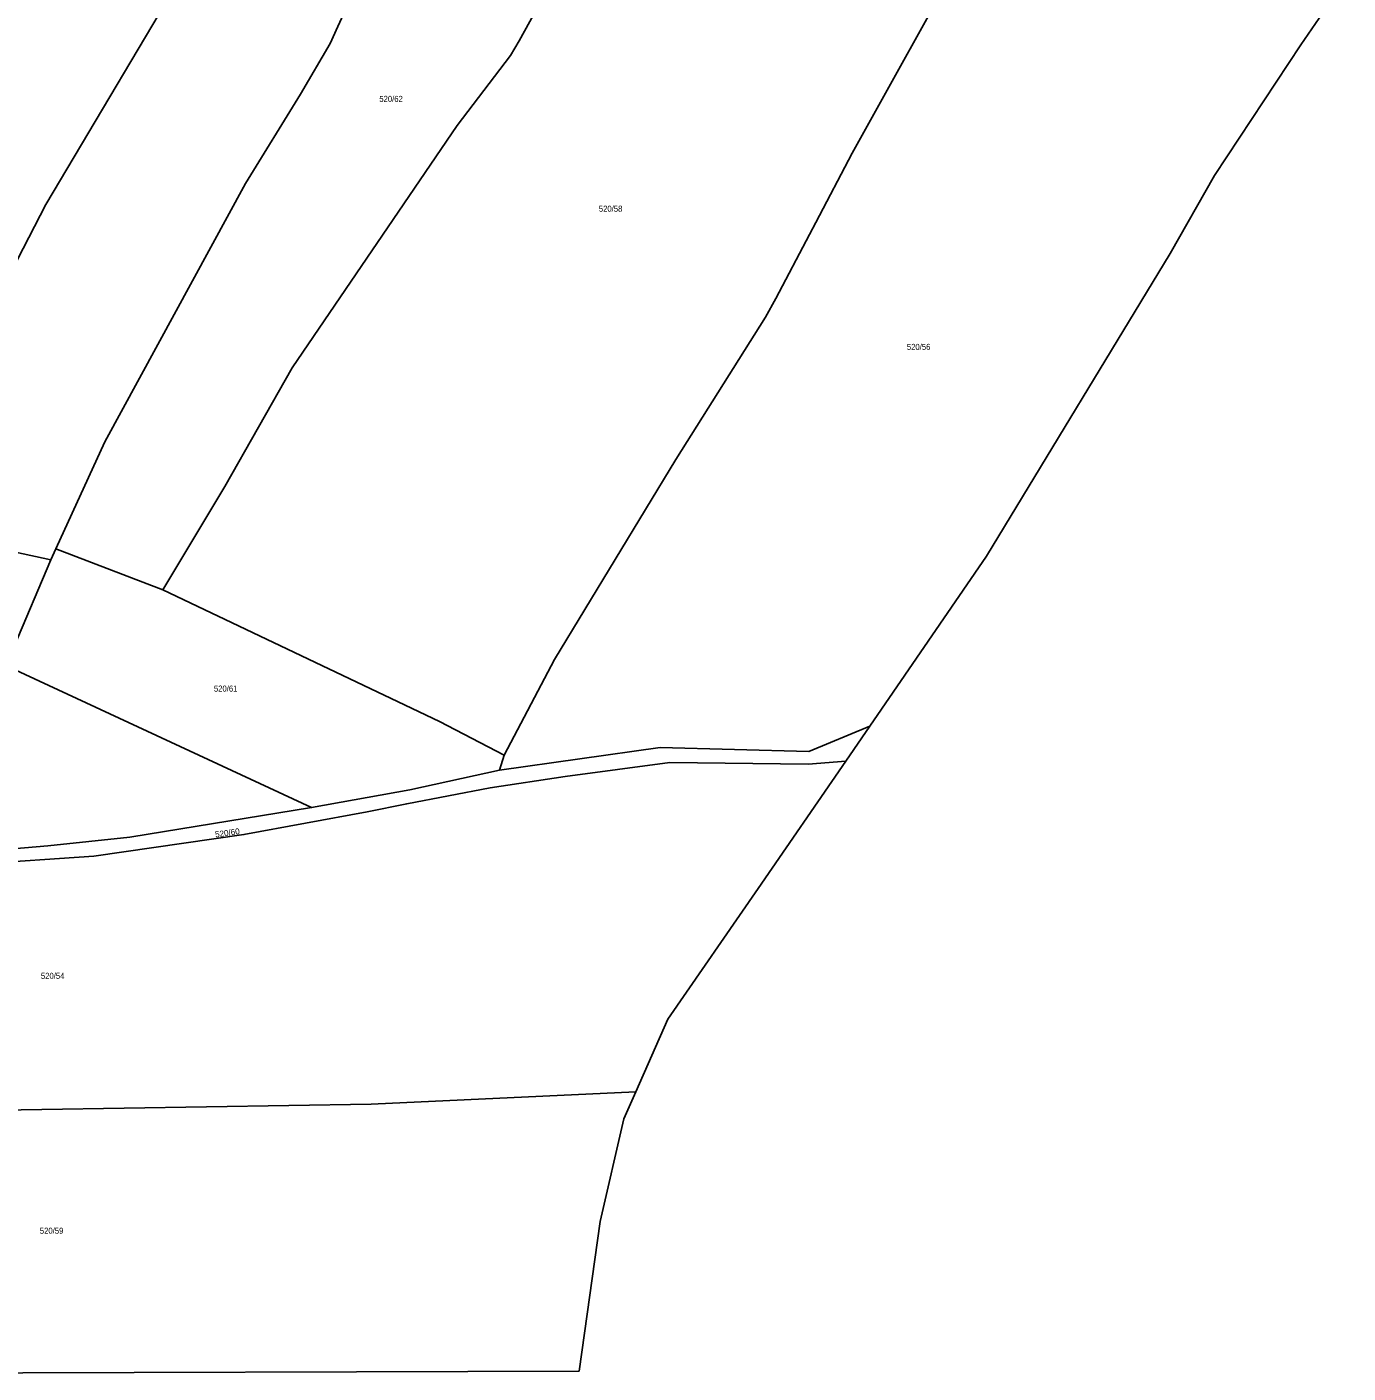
# Model space of a CAD drawing. Extents: x -687135 to -684370, y -1007309 to -1005782.
# Drawn here: x -685309.9 to -684938.9, y -1007302.2 to -1006924.3 of the extents above; entities that cross this region are included whole.
import ezdxf

# ---------------------------------------------------------------- set-up
doc = ezdxf.new("R2010")
doc.units = 0
doc.header["$LTSCALE"] = 0.68
doc.layers.add('1', color=7, linetype='Continuous', lineweight=25)
doc.layers.add('2', color=7, linetype='Continuous')

msp = doc.modelspace()

# ---------------------------------------------------------------- linework, layer by layer
at = {"layer": '1'}
for p, q in [((-684952.13, -1006929.37), (-684938.9, -1006909.84)), ((-685303.16, -1007073.92), (-685301.77, -1007070.79)), ((-685271.73, -1007082.37), (-685301.77, -1007070.79)), ((-685079.98, -1007130.44), (-685073.23, -1007120.63)), ((-685138.93, -1007223.3), (-685129.91, -1007202.86)), ((-685142.28, -1007230.89), (-685138.93, -1007223.3))]:
    msp.add_line(p, q, dxfattribs=at)
for points in [[(-685344.34, -1007065.04), (-685332.49, -1007031.1), (-685312.53, -1006989.57), (-685304.62, -1006974.15), (-685262.73, -1006903.67), (-685259.07, -1006896.13), (-685253.74, -1006885.14), (-685252.41, -1006882.51), (-685229.3, -1006836.82), (-685196.87, -1006776.1)], [(-685301.77, -1007070.79), (-685288.08, -1007040.77), (-685248.53, -1006968.29), (-685233.07, -1006943.13), (-685224.8, -1006928.93), (-685222.62, -1006924.15), (-685216.83, -1006911.45), (-685212.76, -1006902.52), (-685180.81, -1006842.75), (-685155.44, -1006794.14)], [(-685110.47, -1006812.34), (-685128.43, -1006851.09), (-685159.24, -1006905.6), (-685171.68, -1006928.22), (-685174.11, -1006932.29), (-685189.11, -1006951.99), (-685235.44, -1007020.02), (-685254.36, -1007053.37), (-685271.73, -1007082.37)], [(-685021.9, -1006857.13), (-685046.48, -1006902.6), (-685078.16, -1006959.76), (-685088.34, -1006979.18), (-685090.14, -1006982.62), (-685099.65, -1007000.57), (-685102.53, -1007005.79), (-685127.65, -1007045.71), (-685161.8, -1007101.88), (-685175.89, -1007128.8), (-685177.25, -1007132.97)], [(-684988.86, -1006987.88), (-684976.41, -1006966), (-684952.13, -1006929.37)], [(-685073.23, -1007120.63), (-685040.4, -1007072.89), (-685015.17, -1007031.27), (-685013.56, -1007028.61), (-684988.86, -1006987.88)], [(-685313.64, -1007098.44), (-685303.16, -1007073.92), (-685344.34, -1007065.04)], [(-685271.73, -1007082.37), (-685194.03, -1007119.29), (-685175.89, -1007128.8)], [(-685466.75, -1007221.61), (-685450.23, -1007208.57), (-685412.2, -1007182.63), (-685356.43, -1007158.68), (-685304.07, -1007154.21), (-685281.05, -1007151.78), (-685230, -1007143.45), (-685315.69, -1007103.71)], [(-685177.25, -1007132.97), (-685132.11, -1007126.62), (-685090.3, -1007127.69), (-685073.23, -1007120.63)], [(-685079.98, -1007130.44), (-685090.5, -1007131.27), (-685129.34, -1007130.78), (-685158.74, -1007134.7), (-685179.81, -1007137.96), (-685203.27, -1007142.38), (-685214.38, -1007144.66), (-685249, -1007151.04), (-685291.14, -1007157.08), (-685357.28, -1007161.65), (-685410.25, -1007184.52), (-685439.97, -1007204.17), (-685467.01, -1007226.55)], [(-685129.91, -1007202.86), (-685104.58, -1007166.21), (-685079.98, -1007130.44)], [(-685177.25, -1007132.97), (-685202.43, -1007138.45), (-685230, -1007143.45)], [(-685467.65, -1007230.89), (-685213.25, -1007226.72), (-685138.93, -1007223.3)], [(-685154.86, -1007301.68), (-685148.96, -1007259.71), (-685142.28, -1007230.89)], [(-685460.59, -1007298.38), (-685342.44, -1007302.24), (-685154.86, -1007301.68)]]:
    msp.add_lwpolyline(points, dxfattribs=at)

# ---------------------------------------------------------------- texts
at = {"layer": '2', "width": 0.95}
for s, p in [('520/62', (-685210.96, -1006945.35)), ('520/58', (-685149.31, -1006976.179)), ('520/56', (-685062.81, -1007014.98)), ('520/61', (-685257.41, -1007110.91)), ('520/54', (-685305.99, -1007191.559)), ('520/59', (-685306.29, -1007263.12))]:
    msp.add_text(s, height=1.7, dxfattribs=at).set_placement(p)
at = {"layer": '2'}
msp.add_text('520/60', height=1.7, rotation=8, dxfattribs=at).set_placement((-685256.951, -1007151.881))

doc.saveas('drawing.dxf')
